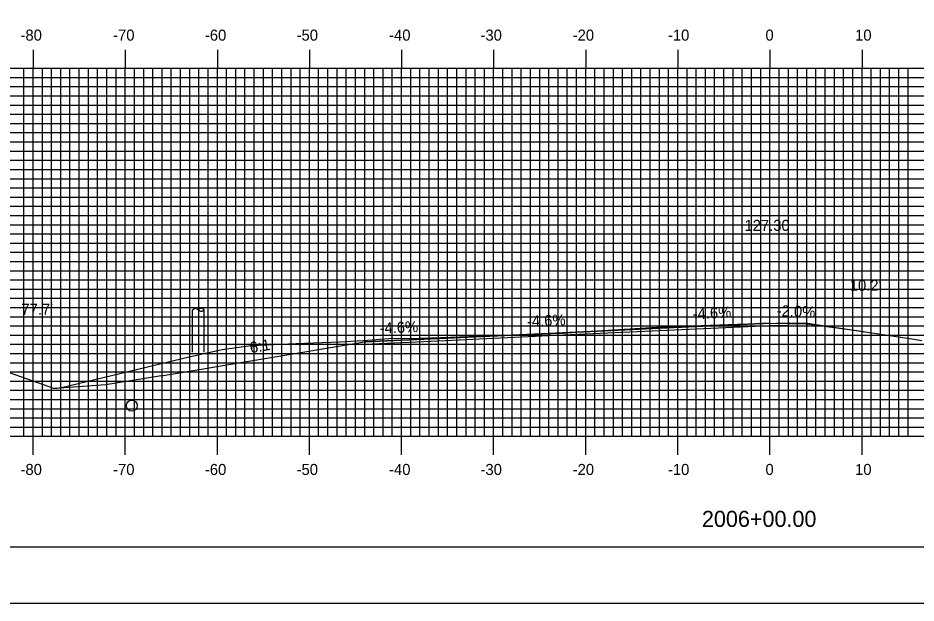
# Model space of a CAD drawing. Extents: x 852320 to 852663, y 366605 to 366825.
# Drawn here: x 852403.8 to 852501.3, y 366604.9 to 366668.5 of the extents above; entities that cross this region are included whole.
import ezdxf

# ---------------------------------------------------------------- set-up
doc = ezdxf.new("R2010")
doc.units = 0
for name, color, linetype in [('ANNOTATION', 7, 'Continuous'), ('BORDER', 7, 'Continuous'), ('D_Roadway_Centerline', 7, 'Continuous'), ('D_Roadway_Centerline_Text', 7, 'Continuous'), ('D_Roadway_Edge_Shoulder', 7, 'Continuous'), ('D_Roadway_Edge_TW', 7, 'Continuous'), ('D_Roadway_SlopeLines', 7, 'Continuous'), ('D_Roadway_SubGrade', 7, 'Continuous'), ('D_Text_Standard', 7, 'Continuous'), ('Default', 7, 'Continuous'), ('H_V ANNOTATION', 7, 'Continuous'), ('M_Roadway_Centerline', 7, 'Continuous'), ('MAJOR', 7, 'Continuous'), ('MINOR', 7, 'Continuous'), ('PLOT BOUNDARY', 7, 'Continuous'), ('S_Drainage_Invert', 7, 'Continuous'), ('S_Roadway_Centerline', 7, 'Continuous'), ('S_Utilities_Pole_StreetLight', 7, 'Continuous')]:
    doc.layers.add(name, color=color, linetype=linetype)

msp = doc.modelspace()

# ---------------------------------------------------------------- linework, layer by layer
at = {"layer": 'BORDER'}
msp.add_lwpolyline([(852335.878, 366611.055), (852655.878, 366611.055), (852655.878, 366821.055), (852335.878, 366821.055)], close=True, dxfattribs=at)
at = {"layer": 'D_Roadway_Centerline'}
msp.add_line((852485.478, 366635.351), (852489.478, 366635.271), dxfattribs=at)
msp.add_lwpolyline([(852419.378, 366629.644), (852441.474, 366633.327), (852441.477, 366633.327), (852449.475, 366633.695), (852449.478, 366633.695), (852449.483, 366633.695), (852461.478, 366634.247), (852473.474, 366634.799), (852473.477, 366634.799), (852479.028, 366635.055), (852485.478, 366635.351), (852489.478, 366635.271)], dxfattribs=at)
at = {"layer": 'D_Roadway_Edge_Shoulder'}
for points in [[(852485.478, 366635.351), (852489.478, 366635.271), (852489.478, 366635.021), (852485.478, 366635.101)], [(852449.478, 366633.695), (852441.477, 366633.327), (852441.477, 366633.077), (852449.478, 366633.445)]]:
    msp.add_lwpolyline(points, close=True, dxfattribs=at)
at = {"layer": 'D_Roadway_Edge_TW'}
for points in [[(852485.478, 366635.351), (852473.477, 366634.799), (852473.477, 366634.549), (852485.478, 366635.101)], [(852461.478, 366634.247), (852449.478, 366633.695), (852449.478, 366633.445), (852461.478, 366633.997)], [(852473.477, 366634.799), (852461.478, 366634.247), (852461.478, 366633.997), (852473.477, 366634.549)]]:
    msp.add_lwpolyline(points, close=True, dxfattribs=at)
msp.add_lwpolyline([(852461.478, 366633.997), (852461.478, 366634.247)], dxfattribs=at)
at = {"layer": 'D_Roadway_SlopeLines'}
msp.add_line((852489.478, 366635.271), (852495.7, 366634.433), dxfattribs=at)
at = {"layer": 'D_Roadway_SubGrade'}
for p, q in [((852419.378, 366629.644), (852413.378, 366628.644)), ((852413.378, 366628.644), (852407.779, 366628.254))]:
    msp.add_line(p, q, dxfattribs=at)
at = {"layer": 'Default'}
for p, q in [((852419.378, 366629.644), (852413.378, 366628.644)), ((852413.378, 366628.644), (852407.779, 366628.254))]:
    msp.add_line(p, q, dxfattribs=at)
at = {"layer": 'MAJOR'}
for p, q in [((852405.478, 366665.059), (852405.478, 366663.055)), ((852415.478, 366665.059), (852415.478, 366663.055)), ((852425.478, 366665.059), (852425.478, 366663.055)), ((852435.478, 366665.059), (852435.478, 366663.055)), ((852445.478, 366665.059), (852445.478, 366663.055)), ((852455.478, 366665.059), (852455.478, 366663.055)), ((852465.478, 366665.059), (852465.478, 366663.055)), ((852475.478, 366665.059), (852475.478, 366663.055)), ((852485.478, 366665.059), (852485.478, 366663.055)), ((852495.478, 366665.059), (852495.478, 366663.055)), ((852345.478, 366663.055), (852625.478, 366663.055)), ((852345.478, 366663.055), (852625.478, 366663.055)), ((852405.478, 366623.055), (852405.478, 366663.055)), ((852415.478, 366623.055), (852415.478, 366663.055)), ((852425.478, 366623.055), (852425.478, 366663.055)), ((852435.478, 366623.055), (852435.478, 366663.055)), ((852445.478, 366623.055), (852445.478, 366663.055)), ((852455.478, 366623.055), (852455.478, 366663.055)), ((852465.478, 366623.055), (852465.478, 366663.055)), ((852475.478, 366623.055), (852475.478, 366663.055)), ((852485.478, 366623.055), (852485.478, 366663.055)), ((852495.478, 366623.055), (852495.478, 366663.055)), ((852345.478, 366658.055), (852625.478, 366658.055)), ((852345.478, 366653.055), (852625.478, 366653.055)), ((852345.478, 366648.055), (852625.478, 366648.055)), ((852345.478, 366643.055), (852625.478, 366643.055)), ((852345.478, 366638.055), (852625.478, 366638.055)), ((852345.478, 366633.055), (852625.478, 366633.055)), ((852345.478, 366628.055), (852625.478, 366628.055)), ((852345.478, 366623.055), (852625.478, 366623.055)), ((852345.478, 366623.055), (852625.478, 366623.055)), ((852405.478, 366621.051), (852405.478, 366623.055)), ((852415.478, 366621.051), (852415.478, 366623.055)), ((852425.478, 366621.051), (852425.478, 366623.055)), ((852435.478, 366621.051), (852435.478, 366623.055)), ((852445.478, 366621.051), (852445.478, 366623.055)), ((852455.478, 366621.051), (852455.478, 366623.055)), ((852465.478, 366621.051), (852465.478, 366623.055)), ((852475.478, 366621.051), (852475.478, 366623.055)), ((852485.478, 366621.051), (852485.478, 366623.055)), ((852495.478, 366621.051), (852495.478, 366623.055))]:
    msp.add_line(p, q, dxfattribs=at)
at = {"layer": 'MINOR'}
for p, q in [((852404.478, 366623.055), (852404.478, 366663.055)), ((852406.478, 366623.055), (852406.478, 366663.055)), ((852407.478, 366623.055), (852407.478, 366663.055)), ((852408.478, 366623.055), (852408.478, 366663.055)), ((852409.478, 366623.055), (852409.478, 366663.055)), ((852410.478, 366623.055), (852410.478, 366663.055)), ((852411.478, 366623.055), (852411.478, 366663.055)), ((852412.478, 366623.055), (852412.478, 366663.055)), ((852413.478, 366623.055), (852413.478, 366663.055)), ((852414.478, 366623.055), (852414.478, 366663.055)), ((852416.478, 366623.055), (852416.478, 366663.055)), ((852417.478, 366623.055), (852417.478, 366663.055)), ((852418.478, 366623.055), (852418.478, 366663.055)), ((852419.478, 366623.055), (852419.478, 366663.055)), ((852420.478, 366623.055), (852420.478, 366663.055)), ((852421.478, 366623.055), (852421.478, 366663.055)), ((852422.478, 366623.055), (852422.478, 366663.055)), ((852423.478, 366623.055), (852423.478, 366663.055)), ((852424.478, 366623.055), (852424.478, 366663.055)), ((852426.478, 366623.055), (852426.478, 366663.055)), ((852427.478, 366623.055), (852427.478, 366663.055)), ((852428.478, 366623.055), (852428.478, 366663.055)), ((852429.478, 366623.055), (852429.478, 366663.055)), ((852430.478, 366623.055), (852430.478, 366663.055)), ((852431.478, 366623.055), (852431.478, 366663.055)), ((852432.478, 366623.055), (852432.478, 366663.055)), ((852433.478, 366623.055), (852433.478, 366663.055)), ((852434.478, 366623.055), (852434.478, 366663.055)), ((852436.478, 366623.055), (852436.478, 366663.055)), ((852437.478, 366623.055), (852437.478, 366663.055)), ((852438.478, 366623.055), (852438.478, 366663.055)), ((852439.478, 366623.055), (852439.478, 366663.055)), ((852440.478, 366623.055), (852440.478, 366663.055)), ((852441.478, 366623.055), (852441.478, 366663.055)), ((852442.478, 366623.055), (852442.478, 366663.055)), ((852443.478, 366623.055), (852443.478, 366663.055)), ((852444.478, 366623.055), (852444.478, 366663.055)), ((852446.478, 366623.055), (852446.478, 366663.055)), ((852447.478, 366623.055), (852447.478, 366663.055)), ((852448.478, 366623.055), (852448.478, 366663.055)), ((852449.478, 366623.055), (852449.478, 366663.055)), ((852450.478, 366623.055), (852450.478, 366663.055)), ((852451.478, 366623.055), (852451.478, 366663.055)), ((852452.478, 366623.055), (852452.478, 366663.055)), ((852453.478, 366623.055), (852453.478, 366663.055)), ((852454.478, 366623.055), (852454.478, 366663.055)), ((852456.478, 366623.055), (852456.478, 366663.055)), ((852457.478, 366623.055), (852457.478, 366663.055)), ((852458.478, 366623.055), (852458.478, 366663.055)), ((852459.478, 366623.055), (852459.478, 366663.055)), ((852460.478, 366623.055), (852460.478, 366663.055)), ((852461.478, 366623.055), (852461.478, 366663.055)), ((852462.478, 366623.055), (852462.478, 366663.055)), ((852463.478, 366623.055), (852463.478, 366663.055)), ((852464.478, 366623.055), (852464.478, 366663.055)), ((852466.478, 366623.055), (852466.478, 366663.055)), ((852467.478, 366623.055), (852467.478, 366663.055)), ((852468.478, 366623.055), (852468.478, 366663.055)), ((852469.478, 366623.055), (852469.478, 366663.055)), ((852470.478, 366623.055), (852470.478, 366663.055)), ((852471.478, 366623.055), (852471.478, 366663.055)), ((852472.478, 366623.055), (852472.478, 366663.055)), ((852473.478, 366623.055), (852473.478, 366663.055)), ((852474.478, 366623.055), (852474.478, 366663.055)), ((852476.478, 366623.055), (852476.478, 366663.055)), ((852477.478, 366623.055), (852477.478, 366663.055)), ((852478.478, 366623.055), (852478.478, 366663.055)), ((852479.478, 366623.055), (852479.478, 366663.055)), ((852480.478, 366623.055), (852480.478, 366663.055)), ((852481.478, 366623.055), (852481.478, 366663.055)), ((852482.478, 366623.055), (852482.478, 366663.055)), ((852483.478, 366623.055), (852483.478, 366663.055)), ((852484.478, 366623.055), (852484.478, 366663.055)), ((852486.478, 366623.055), (852486.478, 366663.055)), ((852487.478, 366623.055), (852487.478, 366663.055)), ((852488.478, 366623.055), (852488.478, 366663.055)), ((852489.478, 366623.055), (852489.478, 366663.055)), ((852490.478, 366623.055), (852490.478, 366663.055)), ((852491.478, 366623.055), (852491.478, 366663.055)), ((852492.478, 366623.055), (852492.478, 366663.055)), ((852493.478, 366623.055), (852493.478, 366663.055)), ((852494.478, 366623.055), (852494.478, 366663.055)), ((852496.478, 366623.055), (852496.478, 366663.055)), ((852497.478, 366623.055), (852497.478, 366663.055)), ((852498.478, 366623.055), (852498.478, 366663.055)), ((852499.478, 366623.055), (852499.478, 366663.055)), ((852500.478, 366623.055), (852500.478, 366663.055)), ((852345.478, 366662.055), (852625.478, 366662.055)), ((852345.478, 366661.055), (852625.478, 366661.055)), ((852345.478, 366660.055), (852625.478, 366660.055)), ((852345.478, 366659.055), (852625.478, 366659.055)), ((852345.478, 366657.055), (852625.478, 366657.055)), ((852345.478, 366656.055), (852625.478, 366656.055)), ((852345.478, 366655.055), (852625.478, 366655.055)), ((852345.478, 366654.055), (852625.478, 366654.055)), ((852345.478, 366652.055), (852625.478, 366652.055)), ((852345.478, 366651.055), (852625.478, 366651.055)), ((852345.478, 366650.055), (852625.478, 366650.055)), ((852345.478, 366649.055), (852625.478, 366649.055)), ((852345.478, 366647.055), (852625.478, 366647.055)), ((852345.478, 366646.055), (852625.478, 366646.055)), ((852345.478, 366645.055), (852625.478, 366645.055)), ((852345.478, 366644.055), (852625.478, 366644.055)), ((852345.478, 366642.055), (852625.478, 366642.055)), ((852345.478, 366641.055), (852625.478, 366641.055)), ((852345.478, 366640.055), (852625.478, 366640.055)), ((852345.478, 366639.055), (852625.478, 366639.055)), ((852345.478, 366637.055), (852625.478, 366637.055)), ((852345.478, 366636.055), (852625.478, 366636.055)), ((852345.478, 366635.055), (852625.478, 366635.055)), ((852345.478, 366634.055), (852625.478, 366634.055)), ((852345.478, 366632.055), (852625.478, 366632.055)), ((852345.478, 366631.055), (852625.478, 366631.055)), ((852345.478, 366630.055), (852625.478, 366630.055)), ((852345.478, 366629.055), (852625.478, 366629.055)), ((852345.478, 366627.055), (852625.478, 366627.055)), ((852345.478, 366626.055), (852625.478, 366626.055)), ((852345.478, 366625.055), (852625.478, 366625.055)), ((852345.478, 366624.055), (852625.478, 366624.055))]:
    msp.add_line(p, q, dxfattribs=at)
at = {"layer": 'PLOT BOUNDARY'}
msp.add_lwpolyline([(852319.691, 366604.937), (852659.691, 366604.937), (852659.691, 366824.937), (852319.691, 366824.937)], close=True, dxfattribs=at)
at = {"layer": 'S_Drainage_Invert'}
msp.add_circle((852416.185, 366626.383), 0.6, dxfattribs=at)
at = {"layer": 'S_Roadway_Centerline'}
msp.add_lwpolyline([(852396.08, 366632.392), (852407.779, 366628.254), (852408.409, 366628.341), (852422.548, 366631.734), (852425.344, 366632.349), (852425.997, 366632.487), (852429.112, 366632.94), (852434.033, 366633.129), (852438.759, 366633.321), (852441.316, 366633.452), (852444.111, 366633.677), (852447.544, 366633.715), (852450.784, 366633.823), (852461.722, 366634.228), (852463.058, 366634.283), (852464.95, 366634.406), (852473.181, 366634.924), (852474.055, 366634.945), (852481.946, 366635.235), (852487.604, 366635.375), (852489.594, 366635.348), (852490.514, 366635.219), (852500.886, 366633.646), (852501.97, 366633.456)], dxfattribs=at)
at = {"layer": 'S_Utilities_Pole_StreetLight'}
for p, q in [((852422.797, 366632.196), (852422.793, 366636.815)), ((852422.797, 366636.815), (852422.953, 366636.925)), ((852423.265, 366636.925), (852423.421, 366636.815)), ((852423.578, 366636.925), (852423.421, 366636.815)), ((852423.421, 366636.815), (852423.578, 366636.704)), ((852424.047, 366636.815), (852423.891, 366636.925)), ((852423.891, 366636.704), (852424.047, 366636.815)), ((852424.047, 366632.196), (852424.043, 366636.815))]:
    msp.add_line(p, q, dxfattribs=at)
for centre, start, end in [((852423.109, 366636.704), 90, 125.26439), ((852423.109, 366636.704), 54.73561, 90), ((852423.734, 366636.704), 90, 125.26439), ((852423.734, 366636.925), 234.73561, 270), ((852423.734, 366636.704), 54.73561, 90), ((852423.734, 366636.925), 270, 305.26439)]:
    msp.add_arc(centre, 0.271, start, end, dxfattribs=at)

# ---------------------------------------------------------------- texts
at = {"layer": 'ANNOTATION'}
for s, rotation, p in [('-4.6%', 2.63362, (852477.12, 366635.769)), ('-2.0%', 357.70909, (852486.194, 366636.124)), ('-4.6%', 2.63381, (852459.121, 366634.941)), ('-4.6%', 2.63354, (852443.118, 366634.205)), ('6:1', 9.4619, (852429.102, 366632.092))]:
    msp.add_text(s, height=1.2, rotation=rotation, dxfattribs=at).set_placement(p)
at = {"layer": 'D_Roadway_Centerline_Text'}
msp.add_text('127.30', height=1.2, dxfattribs=at).set_placement((852482.716, 366645.381))
at = {"layer": 'D_Text_Standard'}
for s, p in [("10.2'", (852494.147, 366638.868)), ("77.7'", (852404.202, 366636.268))]:
    msp.add_text(s, height=1.2, dxfattribs=at).set_placement(p)
at = {"layer": 'H_V ANNOTATION'}
for s, height, p in [('-80', 1.2, (852404.108, 366666.055)), ('-70', 1.2, (852414.161, 366666.055)), ('-60', 1.2, (852424.129, 366666.055)), ('-50', 1.2, (852434.086, 366666.055)), ('-40', 1.2, (852444.129, 366666.055)), ('-30', 1.2, (852454.054, 366666.055)), ('-20', 1.2, (852464.065, 366666.055)), ('-10', 1.2, (852474.407, 366666.055)), ('0', 1.2, (852484.996, 366666.055)), ('10', 1.2, (852494.728, 366666.055)), ('-80', 1.2, (852404.108, 366618.855)), ('-70', 1.2, (852414.161, 366618.855)), ('-60', 1.2, (852424.129, 366618.855)), ('-50', 1.2, (852434.086, 366618.855)), ('-40', 1.2, (852444.129, 366618.855)), ('-30', 1.2, (852454.054, 366618.855)), ('-20', 1.2, (852464.065, 366618.855)), ('-10', 1.2, (852474.407, 366618.855)), ('0', 1.2, (852484.996, 366618.855)), ('10', 1.2, (852494.728, 366618.855)), ('2006+00.00', 1.75, (852478.096, 366613.211))]:
    msp.add_text(s, height=height, dxfattribs=at).set_placement(p)
at = {"layer": 'M_Roadway_Centerline'}
for s, p in [('C', (852473.176, 366634.924)), ('L', (852473.181, 366634.917)), ('C', (852444.106, 366633.677)), ('L', (852444.111, 366633.669))]:
    msp.add_text(s, height=0.0146, dxfattribs=at).set_placement(p)

doc.saveas('drawing.dxf')
